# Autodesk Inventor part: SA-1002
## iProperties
Created: 2004-11
Part Number: SA-1002
Cost Center: 0 lbmass
Document SubType Name: Modeling
Designer: busseym
Manufacturer: Standard
Standards Organization: Custom
Stock Number: P-1267
Density: 1 g/cm^3
CAGE: 1LJX3
Dept. ID: Product Design
Description #2: ---
Finish #1: ---
Finish #2: ---
Material ID: ---
Project Number: ---
Author: busseym
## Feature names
1. Extrusion1
2. Extrusion2
3. Fillet1
4. Extrusion3
5. Mirror1
6. Extrusion4
7. Mirror2
8. Mirror3
